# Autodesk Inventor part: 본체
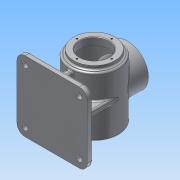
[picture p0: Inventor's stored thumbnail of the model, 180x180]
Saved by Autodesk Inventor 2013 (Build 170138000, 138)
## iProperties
Created: 2015-07
Part Number: 본체
Material: 알루미늄 6061
Document SubType Name: Modeling
Designer: Administrator
Density: 2.71 g/cm^3
Mass: 1241.45 g
Surface Area: 1266.13 cm^2
Volume: 458.098 cm^3
Author: Administrator
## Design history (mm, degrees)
sketch "스케치1"
  geometry: C1 r 45 at (0, 0); 1 further point
  constraints: 1 centre point, 1 coincident
  dimensions: "d0" = 90 diameter of C1
extrude "돌출1" new body sketch "스케치1" distance "d2" = 110; taper "d3" = 0 deg
sketch "스케치2"
  geometry: C1 r 38 at (0, 0); 1 further point
  constraints: 1 centre point, 1 coincident
  dimensions: "d4" = 76 diameter of C1
extrude "돌출2" join sketch "스케치2" distance "d6" = 7; taper "d7" = 0 deg
node "작업 평면1"
sketch "스케치3"
  geometry: L1 (-65, -68)-(65, -68); L2 (65, -68)-(65, -78); L3 (65, -78)-(-65, -78); L4 (-65, -78)-(-65, -68); 2 further points
  constraints: 8 end point, 2 parallel, 1 horizontal, 1 midpoint, 1 perpendicular, 1 vertical alignment
  dimensions: "d9" = 10 distance of L1.end L2.end; "d11" = 78 distance from line of L3 point (0, 0); "d12" = 130 distance of L1.start L1.end
extrude "돌출3" join sketch "스케치3" stored distance "d13" = 110; taper "d14" = 0 deg
node "작업 평면2"
sketch "스케치4"
  geometry: L1 (-29.951, 105)-(-73.534, 105); L2 (-73.534, 105)-(-73.534, 15); L3 (-73.534, 15)-(-29.951, 15); L4 (-29.951, 15)-(-29.951, 105); L5 (-78, 115)-(-68, 115) reference; L6 (-78, 115)-(-78, 5) reference; 1 further point
  constraints: 8 end point, 2 parallel, 1 horizontal, 1 perpendicular
  dimensions: "d16" = 43.58242 distance of L2.end L3.end; "d18" = 90 distance of L1.end L2.end; "d19" = 10 distance between parallel lines of L5 L1; "d20" = 4.46621 distance between parallel lines of L6 L2
extrude "돌출4" join sketch "스케치4" stored distance "d21" = 10; taper "d22" = 0 deg
sketch "스케치5"
  geometry: L1 (-45, 0)-(45, 0); L2 (45, 0)-(45, -73); L3 (45, -73)-(-45, -73); L4 (-45, -73)-(-45, 0); L5 (-65, -78)-(65, -78) reference; 2 further points
  constraints: 8 end point, 2 parallel, 1 coincident, 1 horizontal, 1 midpoint, 1 perpendicular
  dimensions: "d23" = 90 distance of L1.start L1.end; "d25" = 5 distance between parallel lines of L5 L3; "d26" = 73 distance of L1.end L2.end
extrude "돌출5" join sketch "스케치5" stored distance "d27" = 10; taper "d28" = 0 deg
node "작업 평면3"
sketch "스케치6"
  geometry: L1 (0, 0)-(130, 0) reference; C1 r 38 at (65, -55); 1 further point
  constraints: 1 centre point, 1 vertical alignment
  dimensions: "d30" = 76 diameter of C1; "d32" = 55 distance from line of C1.centre L1
extrude "돌출6" join sketch "스케치6" stored distance "d33" = 10; taper "d34" = 0 deg
sketch "스케치7"
  geometry: L1 (0, 110)-(130, 110) reference; L2 (0, 110)-(0, 0) reference; C1 r 7.5 at (15, 110); C2 r 7.5 at (115, 110); C3 r 7.5 at (115, 10); C4 r 7.5 at (15, 10); 1 further point
  constraints: 4 centre point, 3 equal radius, 2 horizontal alignment, 2 vertical alignment
  dimensions: "d35" = 15 diameter of C1; "d37" = 100 distance of C1.centre C2.centre; "d38" = 100 distance of C3.centre C2.centre; "d40" = 15 distance from line of L2 C1.centre; "d112" = 0 distance from line of C2.centre L1
extrude "돌출7" join sketch "스케치7" distance "d41" = 3; taper "d42" = 0 deg
sketch "스케치9"
  geometry: 5 further points
  constraints: 2 horizontal alignment, 2 vertical alignment
  dimensions: "d47" = 64 distance of point (0, -32) point (0, 32); "d49" = 64 distance of point (-32, 0) point (32, 0); "d50" = 32 distance of point (0, 0) point (0, 32); "d51" = 32 distance of point (-32, 0) point (0, 0)
hole "구멍1" sketch "스케치9" at (0, 32), (0, -32), (-32, 0), (32, 0) diameter "d52" = 3.242; stored, may be unused: countersink angle "d56" = 90 deg, drill point angle "d58" = 118 deg; dims "d53" = 8, "d54" = 4, "d55" = 2, "d57" = 10
sketch "스케치10"
  geometry: L1 (65, -55)-(65, 55) reference; L2 (65, -55)-(-65, -55) reference; 6 further points
  constraints: 2 horizontal alignment, 2 vertical alignment
  dimensions: "d59" = 64 distance of point (0, 32) point (0, -32); "d61" = 64 distance of point (-32, 0) point (32, 0); "d62" = 65 distance from line of L1 point (0, 0); "d63" = 55 distance from line of L2 point (0, 0); "d64" = 32 distance of point (0, 0) point (0, 32); "d65" = 32 distance of point (-32, 0) point (0, 0)
hole "구멍2" sketch "스케치10" at (0, 32), (0, -32), (-32, 0), (32, 0) diameter "d66" = 3.242; stored, may be unused: countersink angle "d70" = 90 deg, drill point angle "d72" = 118 deg; dims "d67" = 8, "d68" = 4, "d69" = 2, "d71" = 10
hole "구멍3" diameter "d75" = 54; stored, may be unused: countersink angle "d79" = 90 deg, drill point angle "d81" = 0 deg; dims "d73" = 10, "d74" = 10, "d76" = 8, "d77" = 4, "d78" = 2, "d80" = 14
hole "구멍4" diameter "d84" = 80; stored, may be unused: countersink angle "d88" = 90 deg, drill point angle "d90" = 0 deg; dims "d82" = 10, "d83" = 10, "d85" = 8, "d86" = 4, "d87" = 2, "d89" = 96
hole "구멍5" diameter "d93" = 54; stored, may be unused: countersink angle "d97" = 90 deg, drill point angle "d99" = 0 deg; dims "d91" = 10, "d92" = 10, "d94" = 8, "d95" = 4, "d96" = 2, "d98" = 40
sketch "스케치11"
  geometry: 2 further points
  constraints: 2 coincident, 1 other
feature "엠보싱1" sketch "스케치11" dims "d16" = 43.58242, "d18" = 90, "d19" = 10, "d20" = 4.46621, "d100" = 0.5, "d101" = 0
sketch "스케치12"
  geometry: L1 (-65, -68)-(65, -68); L2 (65, -68)-(65, -78); L3 (65, -78)-(-65, -78); L4 (-65, -78)-(-65, -68); 3 further points
  constraints: 8 end point, 2 coincident, 2 parallel, 1 horizontal, 1 perpendicular
extrude "돌출9" join sketch "스케치12" distance "d108" = 5; taper "d109" = 0 deg
sketch "스케치13"
  geometry: L1 (-65, -68)-(65, -68); L2 (65, -68)-(65, -78); L3 (65, -78)-(-65, -78); L4 (-65, -78)-(-65, -68); 3 further points
  constraints: 8 end point, 2 coincident, 2 parallel, 1 horizontal, 1 perpendicular
extrude "돌출10" join sketch "스케치13" distance "d110" = 15; taper "d111" = 0 deg
chamfer "모따기2" distance "d113" = 1; stored, may be unused: second distance "d114" = 2, angle "d115" = 45 deg
fillet "모깎기3" dims "d116" = 15, "d117" = 3
fillet "모깎기4" dims "d118" = 3
sketch "스케치14"
  geometry: L1 (0, 0)-(100, 0); L2 (100, 0)-(100, -100); L3 (100, -100)-(0, -100); L4 (0, 0)-(0, -100); L5 (100, 15)-(0, 15) reference; L6 (115, -100)-(115, 0) reference; 1 further point
  constraints: 8 end point, 2 perpendicular, 2 vertical alignment, 1 horizontal, 1 horizontal alignment, 1 parallel
  dimensions: "d119" = 100 distance of L3.end L1.start; "d121" = 100 distance of L1.end L1.start; "d122" = 15 distance from line of L1.end L5; "d123" = 15 distance between parallel lines of L6 L2
hole "구멍6" sketch "스케치14" at (0, 0), (0, -100), (100, -100), (100, 0) diameter "d124" = 10; stored, may be unused: countersink angle "d128" = 90 deg, drill point angle "d130" = 0 deg; dims "d125" = 8, "d126" = 4, "d127" = 2, "d129" = 40
node "솔리드1"
other parameters: "d15" = 0
